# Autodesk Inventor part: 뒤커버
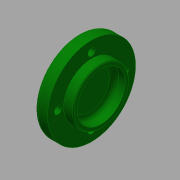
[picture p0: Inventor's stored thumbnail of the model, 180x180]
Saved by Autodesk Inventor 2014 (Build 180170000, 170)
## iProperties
Created: 2015-12
Part Number: 뒤커버
Material: 알루미늄 6061
Document SubType Name: Modeling
Designer: mduedu
Density: 2.71 g/cm^3
Appearance: 진녹색
Author: mduedu
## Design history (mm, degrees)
sketch "스케치1"
  geometry: L1 (0, 0)-(14, 0); L2 (14, 0)-(14, 17.5); L3 (14, 17.5)-(8, 17.5); L4 (8, 17.5)-(8, 27.5); L5 (8, 27.5)-(0, 27.5); L6 (0, 27.5)-(0, 0)
  constraints: 12 end point, 4 parallel, 1 horizontal, 1 perpendicular
  dimensions: "d0" = 14 distance between parallel lines of L2 L6; "d2" = 8 distance of L4.end L5.end; "d3" = 55 diameter of L5 L1; "d4" = 35 diameter of L3 L1
revolve "회전1" sketch "스케치1" stored, may be unused: angle "d5" = 90 deg
hole "구멍1" diameter "d8" = 30; stored, may be unused: countersink angle "d12" = 90 deg, drill point angle "d14" = 0 deg; dims "d9" = 6, "d10" = 4, "d11" = 2, "d13" = 7, "d39" = 10, "d40" = 10
fillet "모깎기3" dims "d38" = 2
fillet "모깎기4" dims "d41" = 3
chamfer "모따기2" distance "d42" = 0.5; stored, may be unused: second distance "d43" = 2, angle "d44" = 45 deg
sketch "스케치2" dims "d45" = 42
  geometry: 6 further points
  constraints: 2 vertical alignment, 1 coincident, 7 other
  dimensions: "d48" = 360 deg dimension on point (0, 0) point (0, 21) (derived)
sketch "스케치3"
  geometry: 4 further points
hole "구멍4" sketch "스케치3" at (-21, 0), (0, -21), (21, 0), (0, 21) diameter "d50" = 4.5; stored, may be unused: countersink angle "d54" = 90 deg, drill point angle "d56" = 0 deg; dims "d51" = 6, "d52" = 8, "d53" = 4.6, "d55" = 8
node "솔리드1"
